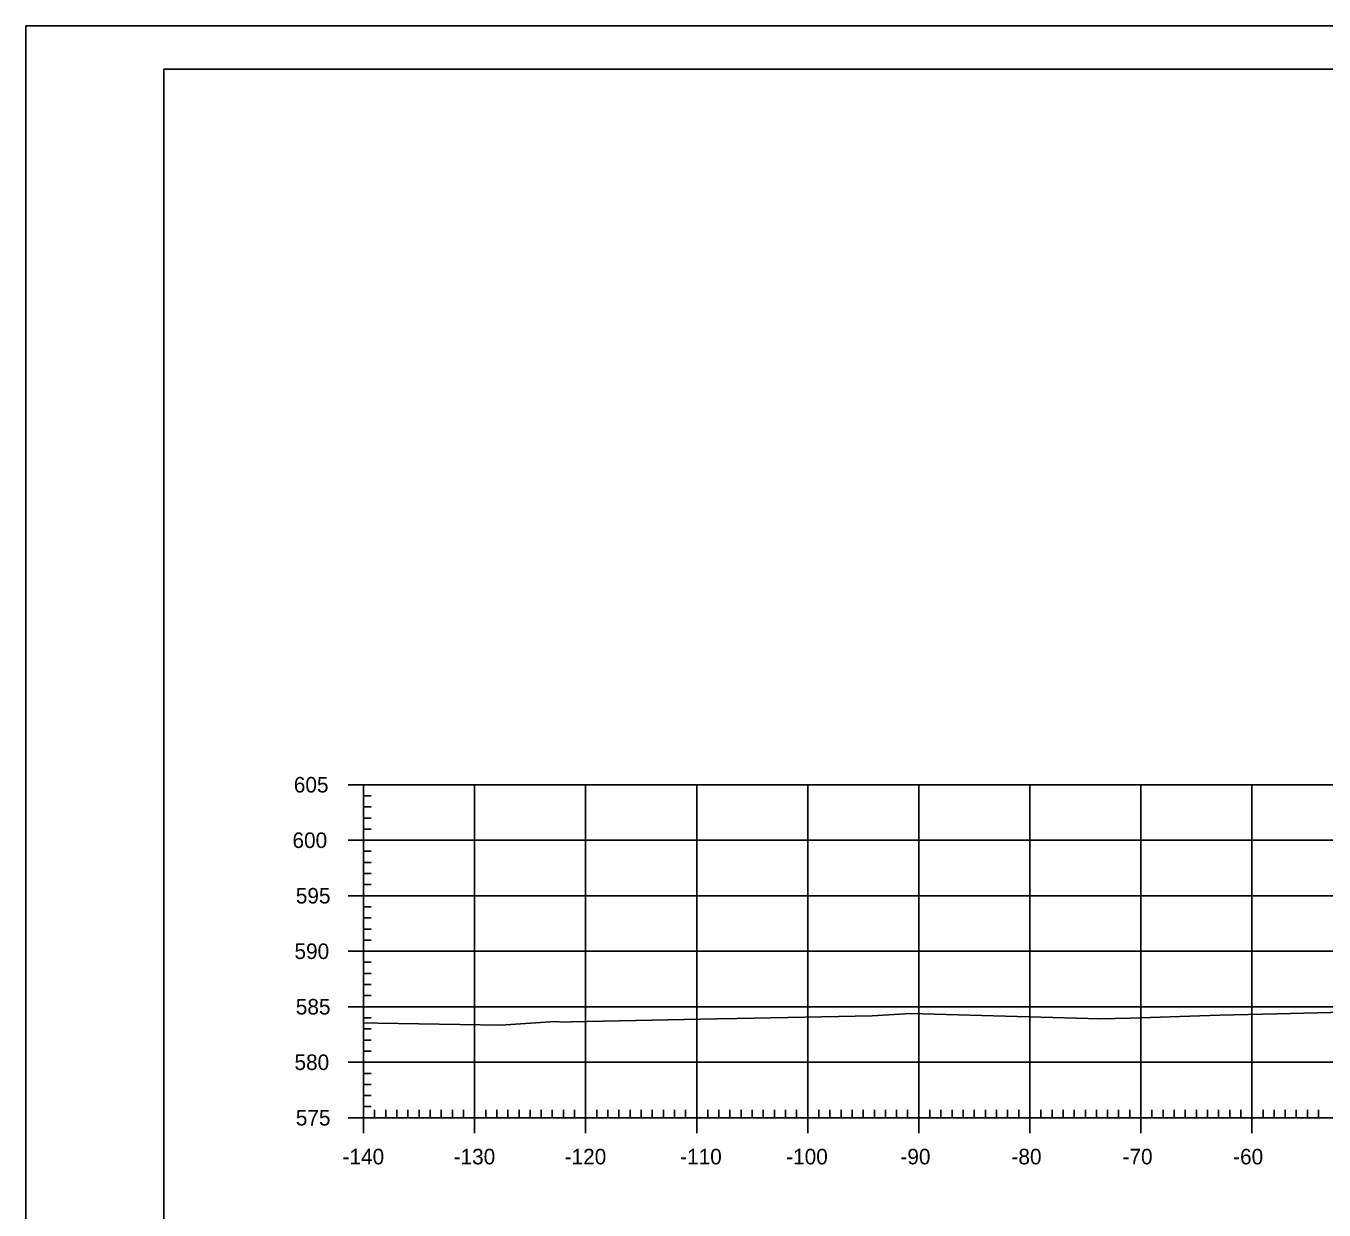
# Model space of a CAD drawing. Extents: x 961436 to 1372525, y 380079 to 2027791.
# Drawn here: x 1370020.1 to 1370137, y 380215.7 to 380322.4 of the extents above; entities that cross this region are included whole.
import ezdxf

# ---------------------------------------------------------------- set-up
doc = ezdxf.new("R2010")
doc.units = 0
for name, color, linetype in [('R_Axis', 7, 'Continuous'), ('R_Axis Annot', 7, 'Continuous'), ('R_Exist Surface', 7, 'Continuous'), ('R_Grid', 7, 'Continuous'), ('R_No Plot', 7, 'Continuous')]:
    doc.layers.add(name, color=color, linetype=linetype)

msp = doc.modelspace()

# ---------------------------------------------------------------- linework, layer by layer
at = {"layer": 'R_Axis'}
for p, q in [((1370049.1, 380254.06), (1370051.9, 380254.06)), ((1370050.5, 380224.06), (1370050.5, 380254.06)), ((1370050.5, 380253.06), (1370051.2, 380253.06)), ((1370050.5, 380252.06), (1370051.2, 380252.06)), ((1370050.5, 380251.06), (1370051.2, 380251.06)), ((1370049.1, 380249.06), (1370051.9, 380249.06)), ((1370050.5, 380250.06), (1370051.2, 380250.06)), ((1370050.5, 380248.06), (1370051.2, 380248.06)), ((1370050.5, 380247.06), (1370051.2, 380247.06)), ((1370050.5, 380246.06), (1370051.2, 380246.06)), ((1370050.5, 380245.06), (1370051.2, 380245.06)), ((1370049.1, 380244.06), (1370051.9, 380244.06)), ((1370050.5, 380243.06), (1370051.2, 380243.06)), ((1370050.5, 380242.06), (1370051.2, 380242.06)), ((1370050.5, 380241.06), (1370051.2, 380241.06)), ((1370050.5, 380240.06), (1370051.2, 380240.06)), ((1370049.1, 380239.06), (1370051.9, 380239.06)), ((1370050.5, 380238.06), (1370051.2, 380238.06)), ((1370050.5, 380237.06), (1370051.2, 380237.06)), ((1370050.5, 380236.06), (1370051.2, 380236.06)), ((1370050.5, 380235.06), (1370051.2, 380235.06)), ((1370049.1, 380234.06), (1370051.9, 380234.06)), ((1370050.5, 380233.06), (1370051.2, 380233.06)), ((1370050.5, 380232.06), (1370051.2, 380232.06)), ((1370050.5, 380231.06), (1370051.2, 380231.06)), ((1370050.5, 380230.06), (1370051.2, 380230.06)), ((1370049.1, 380229.06), (1370051.9, 380229.06)), ((1370050.5, 380228.06), (1370051.2, 380228.06)), ((1370050.5, 380227.06), (1370051.2, 380227.06)), ((1370050.5, 380226.06), (1370051.2, 380226.06)), ((1370050.5, 380222.66), (1370050.5, 380225.46)), ((1370050.5, 380225.06), (1370051.2, 380225.06)), ((1370051.5, 380224.06), (1370051.5, 380224.76)), ((1370052.5, 380224.06), (1370052.5, 380224.76)), ((1370053.5, 380224.06), (1370053.5, 380224.76)), ((1370054.5, 380224.06), (1370054.5, 380224.76)), ((1370055.5, 380224.06), (1370055.5, 380224.76)), ((1370056.5, 380224.06), (1370056.5, 380224.76)), ((1370057.5, 380224.06), (1370057.5, 380224.76)), ((1370058.5, 380224.06), (1370058.5, 380224.76)), ((1370059.5, 380224.06), (1370059.5, 380224.76)), ((1370060.5, 380222.66), (1370060.5, 380225.46)), ((1370061.5, 380224.06), (1370061.5, 380224.76)), ((1370062.5, 380224.06), (1370062.5, 380224.76)), ((1370063.5, 380224.06), (1370063.5, 380224.76)), ((1370064.5, 380224.06), (1370064.5, 380224.76)), ((1370065.5, 380224.06), (1370065.5, 380224.76)), ((1370066.5, 380224.06), (1370066.5, 380224.76)), ((1370067.5, 380224.06), (1370067.5, 380224.76)), ((1370068.5, 380224.06), (1370068.5, 380224.76)), ((1370069.5, 380224.06), (1370069.5, 380224.76)), ((1370070.5, 380222.66), (1370070.5, 380225.46)), ((1370071.5, 380224.06), (1370071.5, 380224.76)), ((1370072.5, 380224.06), (1370072.5, 380224.76)), ((1370073.5, 380224.06), (1370073.5, 380224.76)), ((1370074.5, 380224.06), (1370074.5, 380224.76)), ((1370075.5, 380224.06), (1370075.5, 380224.76)), ((1370076.5, 380224.06), (1370076.5, 380224.76)), ((1370077.5, 380224.06), (1370077.5, 380224.76)), ((1370078.5, 380224.06), (1370078.5, 380224.76)), ((1370079.5, 380224.06), (1370079.5, 380224.76)), ((1370080.5, 380222.66), (1370080.5, 380225.46)), ((1370081.5, 380224.06), (1370081.5, 380224.76)), ((1370082.5, 380224.06), (1370082.5, 380224.76)), ((1370083.5, 380224.06), (1370083.5, 380224.76)), ((1370084.5, 380224.06), (1370084.5, 380224.76)), ((1370085.5, 380224.06), (1370085.5, 380224.76)), ((1370086.5, 380224.06), (1370086.5, 380224.76)), ((1370087.5, 380224.06), (1370087.5, 380224.76)), ((1370088.5, 380224.06), (1370088.5, 380224.76)), ((1370089.5, 380224.06), (1370089.5, 380224.76)), ((1370090.5, 380222.66), (1370090.5, 380225.46)), ((1370091.5, 380224.06), (1370091.5, 380224.76)), ((1370092.5, 380224.06), (1370092.5, 380224.76)), ((1370093.5, 380224.06), (1370093.5, 380224.76)), ((1370094.5, 380224.06), (1370094.5, 380224.76)), ((1370095.5, 380224.06), (1370095.5, 380224.76)), ((1370096.5, 380224.06), (1370096.5, 380224.76)), ((1370097.5, 380224.06), (1370097.5, 380224.76)), ((1370098.5, 380224.06), (1370098.5, 380224.76)), ((1370099.5, 380224.06), (1370099.5, 380224.76)), ((1370100.5, 380222.66), (1370100.5, 380225.46)), ((1370101.5, 380224.06), (1370101.5, 380224.76)), ((1370102.5, 380224.06), (1370102.5, 380224.76)), ((1370103.5, 380224.06), (1370103.5, 380224.76)), ((1370104.5, 380224.06), (1370104.5, 380224.76)), ((1370105.5, 380224.06), (1370105.5, 380224.76)), ((1370106.5, 380224.06), (1370106.5, 380224.76)), ((1370107.5, 380224.06), (1370107.5, 380224.76)), ((1370108.5, 380224.06), (1370108.5, 380224.76)), ((1370109.5, 380224.06), (1370109.5, 380224.76)), ((1370110.5, 380222.66), (1370110.5, 380225.46)), ((1370111.5, 380224.06), (1370111.5, 380224.76)), ((1370112.5, 380224.06), (1370112.5, 380224.76)), ((1370113.5, 380224.06), (1370113.5, 380224.76)), ((1370114.5, 380224.06), (1370114.5, 380224.76)), ((1370115.5, 380224.06), (1370115.5, 380224.76)), ((1370116.5, 380224.06), (1370116.5, 380224.76)), ((1370117.5, 380224.06), (1370117.5, 380224.76)), ((1370118.5, 380224.06), (1370118.5, 380224.76)), ((1370119.5, 380224.06), (1370119.5, 380224.76)), ((1370120.5, 380222.66), (1370120.5, 380225.46)), ((1370121.5, 380224.06), (1370121.5, 380224.76)), ((1370122.5, 380224.06), (1370122.5, 380224.76)), ((1370123.5, 380224.06), (1370123.5, 380224.76)), ((1370124.5, 380224.06), (1370124.5, 380224.76)), ((1370125.5, 380224.06), (1370125.5, 380224.76)), ((1370126.5, 380224.06), (1370126.5, 380224.76)), ((1370127.5, 380224.06), (1370127.5, 380224.76)), ((1370128.5, 380224.06), (1370128.5, 380224.76)), ((1370129.5, 380224.06), (1370129.5, 380224.76)), ((1370130.5, 380222.66), (1370130.5, 380225.46)), ((1370131.5, 380224.06), (1370131.5, 380224.76)), ((1370132.5, 380224.06), (1370132.5, 380224.76)), ((1370133.5, 380224.06), (1370133.5, 380224.76)), ((1370134.5, 380224.06), (1370134.5, 380224.76)), ((1370135.5, 380224.06), (1370135.5, 380224.76)), ((1370136.5, 380224.06), (1370136.5, 380224.76)), ((1370049.1, 380224.06), (1370051.9, 380224.06)), ((1370050.5, 380224.06), (1370330.5, 380224.06))]:
    msp.add_line(p, q, dxfattribs=at)
at = {"layer": 'R_Exist Surface'}
msp.add_lwpolyline([(1370050.5, 380232.62), (1370051.8, 380232.59), (1370062.87, 380232.39), (1370067.77, 380232.72), (1370068.5, 380232.68), (1370069.19, 380232.69), (1370082.29, 380232.97), (1370084.15, 380233), (1370096.29, 380233.25), (1370099.78, 380233.45), (1370116.83, 380232.96), (1370119.55, 380233.02), (1370127.61, 380233.29), (1370132.76, 380233.41), (1370141.26, 380233.62)], dxfattribs=at)
at = {"layer": 'R_Grid'}
for p, q in [((1370050.5, 380254.06), (1370330.5, 380254.06)), ((1370050.5, 380224.06), (1370050.5, 380254.06)), ((1370060.5, 380224.06), (1370060.5, 380254.06)), ((1370070.5, 380224.06), (1370070.5, 380254.06)), ((1370080.5, 380224.06), (1370080.5, 380254.06)), ((1370090.5, 380224.06), (1370090.5, 380254.06)), ((1370100.5, 380224.06), (1370100.5, 380254.06)), ((1370110.5, 380224.06), (1370110.5, 380254.06)), ((1370120.5, 380224.06), (1370120.5, 380254.06)), ((1370130.5, 380224.06), (1370130.5, 380254.06)), ((1370050.5, 380249.06), (1370330.5, 380249.06)), ((1370050.5, 380244.06), (1370330.5, 380244.06)), ((1370050.5, 380239.06), (1370330.5, 380239.06)), ((1370050.5, 380234.06), (1370330.5, 380234.06)), ((1370050.5, 380229.06), (1370330.5, 380229.06)), ((1370050.5, 380224.06), (1370330.5, 380224.06))]:
    msp.add_line(p, q, dxfattribs=at)
at = {"layer": 'R_No Plot'}
for p, q in [((1370020.1, 380322.41), (1370353.44, 380322.41)), ((1370032.5, 380318.52), (1370348.68, 380318.52)), ((1370032.5, 380113.06), (1370032.5, 380318.52))]:
    msp.add_line(p, q, dxfattribs=at)
for points in [[(1370020.1, 380322.41), (1370353.44, 380322.41), (1370353.44, 380109.08), (1370020.1, 380109.08)], [(1370266.42, 380318.52), (1370286.04, 380318.52), (1370286.04, 380308.64), (1370302.16, 380308.64), (1370325.36, 380308.64), (1370325.48, 380280.48), (1370348.68, 380280.48), (1370348.68, 380113.06), (1370032.5, 380113.06), (1370032.5, 380318.52)]]:
    msp.add_lwpolyline(points, close=True, dxfattribs=at)

# ---------------------------------------------------------------- texts
at = {"layer": 'R_Axis Annot'}
for s, p in [('605', (1370044.22, 380253.36)), ('600', (1370044.1, 380248.36)), ('595', (1370044.4, 380243.36)), ('590', (1370044.28, 380238.36)), ('585', (1370044.4, 380233.36)), ('580', (1370044.28, 380228.36)), ('575', (1370044.4, 380223.36)), ('-140', (1370048.61, 380219.86)), ('-130', (1370058.61, 380219.86)), ('-120', (1370068.61, 380219.86)), ('-110', (1370079.01, 380219.86)), ('-100', (1370088.56, 380219.86)), ('-90', (1370098.85, 380219.86)), ('-80', (1370108.85, 380219.86)), ('-70', (1370118.85, 380219.86)), ('-60', (1370128.81, 380219.86))]:
    msp.add_text(s, height=1.4, dxfattribs=at).set_placement(p)

doc.saveas('drawing.dxf')
